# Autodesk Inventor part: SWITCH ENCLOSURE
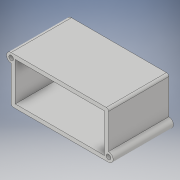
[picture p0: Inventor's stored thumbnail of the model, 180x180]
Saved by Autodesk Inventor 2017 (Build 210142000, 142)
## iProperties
Created: 2016-08
Part Number: SWITCH ENCLOSURE
Material: Generic
Document SubType Name: Modeling
Designer: Stan
Density: 1 g/cm^3
Appearance: Default
Author: Stan
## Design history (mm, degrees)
sketch "Sketch1"
  geometry: L1 (-46.831, 15.875)-(19.844, 15.875); L2 (19.844, 15.875)-(19.844, -15.875); L3 (19.844, -15.875)-(-46.831, -15.875); L4 (-46.831, -15.875)-(-46.831, 15.875); 1 further point
  constraints: 8 end point, 2 parallel, 1 horizontal, 1 perpendicular
  dimensions: "d0" = 31.75 distance of L3.end L1.start; "d1" = 15.875 distance from line of point (0, 0) L1; "d2" = 66.675 distance of L2.end L3.end; "d23" = 19.84375 distance from line of L2 point (0, 0)
extrude "Extrusion1" new body sketch "Sketch1" distance "d4" = 41.275; taper "d5" = 0 deg
sketch "Sketch2"
  geometry: L1 (-44.018, 13.208)-(17.018, 13.208); L2 (17.018, 13.208)-(17.018, -13.208); L3 (17.018, -13.208)-(-44.018, -13.208); L4 (-44.018, -13.208)-(-44.018, 13.208); 1 further point
  constraints: 8 end point, 2 parallel, 1 horizontal, 1 perpendicular
  dimensions: "d6" = 61.0362 distance of L1.start L1.end; "d8" = 26.416 distance of L1.end L2.end; "d9" = 13.208 distance from line of L1 point (0, 0); "d24" = 17.018 distance from line of point (0, 0) L2
extrude "Extrusion2" cut sketch "Sketch2" distance "d10" = 38.1; taper "d11" = 0 deg
sketch "Sketch7"
  geometry: L1 (0, 0)-(41.275, 0) reference; L2 (41.275, 31.75)-(41.275, 0) reference; C1 r 5.969 at (12.7, 12.7); 1 further point
  constraints: 1 centre point
  dimensions: "d25" = 11.938 diameter of C1; "d28" = 12.7 distance from line of C1.centre L1; "d29" = 28.575 distance from line of L2 C1.centre
extrude "Extrusion6" cut sketch "Sketch7" distance "d30" = 3.175; taper "d31" = 0 deg
sketch "Sketch8"
  geometry: L1 (-46.831, -15.875)-(-46.831, 15.875) reference; L2 (19.844, -15.875)-(19.844, 15.875) reference; A1 r 3.175 centre (-46.831, 12.7) between (-46.831, 15.875) and (-46.831, 9.525); A2 r 3.175 centre (19.844, -12.7) between (19.844, -15.875) and (19.844, -9.525); 1 further point
  constraints: 4 point on circle, 4 point on line, 2 centre point, 2 end point
  dimensions: "d32" = 6.35 diameter of A1; "d33" = 6.35 diameter of A2
extrude "Extrusion7" join sketch "Sketch8" distance "d34" = 41.275; taper "d35" = 0 deg
sketch "Sketch9"
  geometry: C1 r 1.588 at (-46.831, 12.7); C2 r 1.588 at (19.844, -12.7); A1 r 3.175 centre (-46.831, 12.7) between (-46.831, 15.875) and (-46.831, 9.525) reference; A2 r 3.175 centre (19.844, -12.7) between (19.844, -15.875) and (19.844, -9.525) reference; 1 further point
  constraints: 2 centre point, 2 coincident
  dimensions: "d36" = 3.175 diameter of C1; "d37" = 3.175 diameter of C2
extrude "Extrusion8" cut sketch "Sketch9" distance "d38" = 41.275; taper "d39" = 0 deg
fillet "Fillet1" dims "d40" = 1.5875
fillet "Fillet2" dims "d41" = 1.5875
sketch "Sketch10"
  geometry: C1 r 2.381 at (0, 0); 1 further point
  constraints: 1 centre point, 1 coincident
  dimensions: "d42" = 4.7625 diameter of C1
extrude "Extrusion9" cut sketch "Sketch10" distance "d43" = 3.175; taper "d44" = 0 deg
body "Solid1"
